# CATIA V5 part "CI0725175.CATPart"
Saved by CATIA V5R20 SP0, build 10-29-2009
Part number: CI0725175
Bounding box of the stored display mesh (mm): x -24 to 24, y -20.111 to 209.5, z -24.221 to 28.662
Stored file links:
  C:\Users\Raffaele\Desktop\3D X SITO CF\BOLEX\19-INCLINED ASSEMBLY REF_CI\CI0725175.CATPart
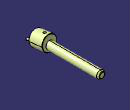
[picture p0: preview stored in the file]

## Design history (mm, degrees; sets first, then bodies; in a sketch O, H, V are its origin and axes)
Set1
  DatumSurface1 to DatumSurface16 "MANIFOLD_SOLID_BREP #393"
  DatumSurface17 to DatumSurface39 "MANIFOLD_SOLID_BREP #1138"
Body1 (main body)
